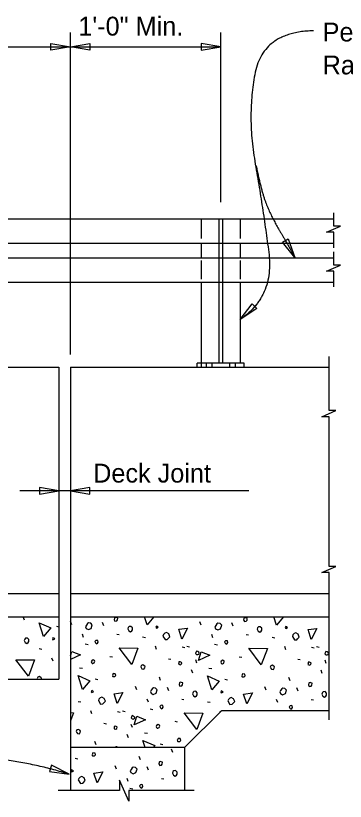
# Model space of a CAD drawing. Extents: x 120680.2 to 120752.3, y 120667.6 to 120707.3.
# Drawn here: x 120701.61 to 120705.13, y 120695.16 to 120703.55 of the extents above; entities that cross this region are included whole.
import ezdxf

# ---------------------------------------------------------------- set-up
doc = ezdxf.new("R2010")
doc.units = 0
for name, color, linetype in [('Dimension', 7, 'Continuous'), ('ParapetConc', 7, 'Continuous'), ('PedRail', 7, 'Continuous'), ('TextStructures', 7, 'Continuous')]:
    doc.layers.add(name, color=color, linetype=linetype)

msp = doc.modelspace()

# ---------------------------------------------------------------- linework, layer by layer
at = {"layer": 'Dimension'}
for p, q in [((120702.1898, 120699.9295), (120702.1898, 120703.3696)), ((120703.7953, 120701.556), (120703.7953, 120703.3696)), ((120698.746, 120703.2151), (120702.1898, 120703.2151)), ((120704.094, 120698.4727), (120701.6496, 120698.4727))]:
    msp.add_line(p, q, dxfattribs=at)
for points in [[(120701.9815, 120703.2503), (120702.1898, 120703.2151), (120701.9815, 120703.1798)], [(120702.398, 120703.1798), (120702.1898, 120703.2151), (120702.398, 120703.2503)], [(120703.7953, 120703.2151), (120703.587, 120703.2503), (120703.587, 120703.1798)], [(120704.5166, 120701.1656), (120704.5874, 120700.9666), (120704.455, 120701.1312)], [(120704.1797, 120700.4209), (120704.0036, 120700.3043), (120704.1314, 120700.4724)], [(120702.0673, 120698.4727), (120701.859, 120698.5079), (120701.859, 120698.4374)], [(120702.1898, 120698.4727), (120702.398, 120698.4374), (120702.398, 120698.5079)], [(120702.1768, 120695.4468), (120701.9878, 120695.5411), (120701.9673, 120695.4736)]]:
    msp.add_lwpolyline(points, close=True, dxfattribs=at)
for points in [[(120702.1898, 120703.2151), (120703.7953, 120703.2151)], [(120705.0043, 120701.069), (120705.0043, 120701.2356), (120704.9268, 120701.2356), (120705.0768, 120701.3018), (120705.0043, 120701.3018), (120705.0043, 120701.4427)], [(120705.0043, 120700.7007), (120705.0043, 120700.8189), (120704.9268, 120700.8189), (120705.0768, 120700.8852), (120705.0043, 120700.8852), (120705.0043, 120701.026)], [(120705.0043, 120700.6523), (120705.0043, 120700.7007)], [(120704.9532, 120698.3779), (120704.9532, 120699.2651), (120704.8757, 120699.2651), (120705.0257, 120699.3314), (120704.9532, 120699.3314), (120704.9532, 120699.907)], [(120704.9532, 120696.0279), (120704.9532, 120697.6005), (120704.8757, 120697.6005), (120705.0257, 120697.6668), (120704.9532, 120697.6668), (120704.9532, 120698.3779)], [(120703.5106, 120695.2732), (120702.8136, 120695.2732), (120702.8136, 120695.157), (120702.7142, 120695.382), (120702.7142, 120695.2732), (120702.059, 120695.2732)]]:
    msp.add_lwpolyline(points, dxfattribs=at)
for points in [[(120704.7863, 120703.3873), (120704.2451, 120703.3779), (120704.0759, 120702.477), (120704.2447, 120701.5052), (120704.371, 120700.5545), (120704.0036, 120700.3043)], [(120704.1744, 120701.9453), (120704.2306, 120701.6629), (120704.3399, 120701.3964), (120704.4841, 120701.1516), (120704.5874, 120700.9666)], [(120702.1768, 120695.4468), (120701.526, 120695.6444), (120700.8623, 120695.6444)]]:
    msp.add_open_spline(points, degree=2, dxfattribs=at)
at = {"layer": 'ParapetConc'}
for p, q in [((120695.9996, 120699.7946), (120702.0673, 120699.7946)), ((120702.0673, 120699.7946), (120702.0673, 120696.4613)), ((120702.1898, 120699.7946), (120702.1898, 120695.2732)), ((120702.1898, 120699.7946), (120704.9532, 120699.7946)), ((120695.9996, 120697.3779), (120702.0673, 120697.3779)), ((120702.1898, 120697.3779), (120704.9532, 120697.3779)), ((120695.9996, 120697.1279), (120702.0673, 120697.1279)), ((120702.1898, 120697.1279), (120704.9532, 120697.1279)), ((120695.9996, 120696.4612), (120702.0673, 120696.4612)), ((120703.4098, 120695.7305), (120703.8071, 120696.1279)), ((120703.8071, 120696.1279), (120704.9532, 120696.1279)), ((120703.4098, 120695.7305), (120702.1898, 120695.7305)), ((120703.4098, 120695.7305), (120703.4098, 120695.2732))]:
    msp.add_line(p, q, dxfattribs=at)
at = {"layer": 'PedRail'}
for p, q in [((120700.4577, 120701.3779), (120705.0043, 120701.3779)), ((120703.5869, 120701.3779), (120703.5869, 120701.1671)), ((120703.7744, 120701.3779), (120703.7744, 120700.7007)), ((120703.8161, 120701.3779), (120703.8161, 120700.7007)), ((120704.0036, 120701.3779), (120704.0036, 120701.1671)), ((120700.4577, 120701.1174), (120705.0043, 120701.1174)), ((120703.5869, 120701.1084), (120703.5869, 120700.9613)), ((120704.0036, 120701.1084), (120704.0036, 120700.9613)), ((120700.4577, 120700.9613), (120703.5869, 120700.9613)), ((120702.1735, 120700.9613), (120705.0043, 120700.9613)), ((120703.5869, 120700.9345), (120703.5869, 120700.7342)), ((120704.0036, 120700.9345), (120704.0036, 120700.7342)), ((120700.4577, 120700.7007), (120703.5869, 120700.7007)), ((120702.1735, 120700.7007), (120705.0043, 120700.7007)), ((120703.5869, 120700.7007), (120703.5869, 120699.7946)), ((120703.7744, 120700.7007), (120703.7744, 120699.8363)), ((120703.8161, 120700.7007), (120703.8161, 120699.8363)), ((120704.0036, 120700.7007), (120704.0036, 120699.8363)), ((120704.0453, 120699.8363), (120703.5453, 120699.8363)), ((120703.5453, 120699.7946), (120703.5453, 120699.8363)), ((120703.639, 120699.8363), (120703.639, 120699.7946)), ((120703.7015, 120699.8363), (120703.7015, 120699.7946)), ((120703.889, 120699.8363), (120703.889, 120699.7946)), ((120703.9515, 120699.8363), (120703.9515, 120699.7946)), ((120704.0453, 120699.7946), (120704.0453, 120699.8363)), ((120701.6998, 120697.0923), (120701.6856, 120697.1277)), ((120702.2045, 120697.0405), (120702.1904, 120697.0759)), ((120702.5475, 120697.0299), (120702.5333, 120697.0653)), ((120703.5869, 120697.037), (120703.5728, 120697.0723)), ((120703.9298, 120697.0264), (120703.9157, 120697.0618)), ((120702.0392, 120697.0287), (120702.0673, 120697.0217)), ((120702.33, 120696.908), (120702.3176, 120696.9416)), ((120702.6854, 120696.9416), (120702.7101, 120696.938)), ((120702.9611, 120696.9133), (120702.9912, 120696.908)), ((120703.7124, 120696.9044), (120703.7, 120696.938)), ((120704.0678, 120696.938), (120704.0925, 120696.9345)), ((120704.3435, 120696.9097), (120704.3736, 120696.9044)), ((120701.8554, 120696.7883), (120701.8854, 120696.783)), ((120702.3477, 120696.8372), (120702.3778, 120696.8319)), ((120703.1096, 120696.7789), (120703.0972, 120696.8125)), ((120703.3836, 120696.8054), (120703.4119, 120696.7983)), ((120703.4349, 120696.8143), (120703.4632, 120696.8072)), ((120703.7301, 120696.8337), (120703.7601, 120696.8284)), ((120704.492, 120696.7754), (120704.4796, 120696.809)), ((120704.766, 120696.8019), (120704.7943, 120696.7948)), ((120704.8173, 120696.8107), (120704.8456, 120696.8036)), ((120702.6111, 120696.7047), (120702.6376, 120696.6994)), ((120703.9935, 120696.7011), (120704.02, 120696.6958)), ((120702.0038, 120696.6539), (120701.9914, 120696.6875)), ((120703.2369, 120696.6799), (120703.2634, 120696.6746)), ((120703.5409, 120696.634), (120703.5286, 120696.6676)), ((120704.6193, 120696.6764), (120704.6458, 120696.6711)), ((120704.9233, 120696.6304), (120704.911, 120696.664)), ((120702.2876, 120696.5827), (120702.3194, 120696.5792)), ((120703.4985, 120696.5244), (120703.4844, 120696.5597)), ((120703.67, 120696.5792), (120703.7018, 120696.5756)), ((120704.8809, 120696.5208), (120704.8668, 120696.5562)), ((120702.4556, 120696.4643), (120702.4838, 120696.4572)), ((120703.1538, 120696.4483), (120703.1397, 120696.4837)), ((120703.838, 120696.4607), (120703.8662, 120696.4536)), ((120704.5362, 120696.4448), (120704.5221, 120696.4802)), ((120702.8975, 120696.3476), (120702.8833, 120696.3829)), ((120703.2404, 120696.337), (120703.2263, 120696.3723)), ((120704.2799, 120696.3441), (120704.2657, 120696.3794)), ((120704.6228, 120696.3334), (120704.6087, 120696.3688)), ((120702.2717, 120696.2239), (120702.3018, 120696.2185)), ((120703.023, 120696.215), (120703.0106, 120696.2486)), ((120703.3783, 120696.2486), (120703.4031, 120696.2451)), ((120703.6541, 120696.2203), (120703.6842, 120696.215)), ((120704.4054, 120696.2115), (120704.393, 120696.2451)), ((120704.7607, 120696.2451), (120704.7855, 120696.2415)), ((120702.4202, 120696.0895), (120702.4078, 120696.1231)), ((120702.6942, 120696.116), (120702.7225, 120696.1089)), ((120702.7455, 120696.1248), (120702.7737, 120696.1178)), ((120703.0407, 120696.1443), (120703.0707, 120696.139)), ((120703.7925, 120696.1133), (120703.7902, 120696.1195)), ((120702.5475, 120695.9905), (120702.574, 120695.9852)), ((120702.8515, 120695.9445), (120702.8392, 120695.9781)), ((120703.3041, 120696.0117), (120703.3306, 120696.0064)), ((120702.8091, 120695.8349), (120702.7949, 120695.8703)), ((120702.9806, 120695.8897), (120703.0124, 120695.8862)), ((120702.4644, 120695.7589), (120702.4503, 120695.7943)), ((120703.1485, 120695.7713), (120703.1768, 120695.7642)), ((120703.2828, 120695.677), (120703.2686, 120695.7123)), ((120702.2398, 120695.6169), (120702.2681, 120695.6098)), ((120702.9381, 120695.601), (120702.9239, 120695.6364)), ((120702.6818, 120695.5002), (120702.6676, 120695.5356)), ((120703.0247, 120695.4896), (120703.0106, 120695.525)), ((120702.8073, 120695.3677), (120702.7949, 120695.4013)), ((120703.1626, 120695.4013), (120703.1873, 120695.3977)), ((120702.8249, 120695.2969), (120702.855, 120695.2916))]:
    msp.add_line(p, q, dxfattribs=at)
for points in [[(120702.6571, 120697.0971), (120702.6659, 120697.0812), (120702.6854, 120697.083), (120702.6942, 120697.0954), (120702.696, 120697.1148), (120702.6836, 120697.1201), (120702.6747, 120697.1219), (120702.6642, 120697.1183), (120702.6606, 120697.1148), (120702.6571, 120697.0971)], [(120703.0088, 120697.0423), (120702.981, 120697.1279)], [(120703.0813, 120697.1279), (120703.0088, 120697.0423)], [(120704.3912, 120697.0388), (120704.3623, 120697.1279)], [(120704.4667, 120697.1279), (120704.3912, 120697.0388)], [(120701.9031, 120696.9173), (120701.8554, 120697.0641), (120701.9809, 120697.0092), (120701.9031, 120696.9173)], [(120702.3583, 120697.0034), (120702.3813, 120696.991), (120702.4113, 120697.0034), (120702.4237, 120697.0405), (120702.406, 120697.0582), (120702.3831, 120697.0635), (120702.3724, 120697.0565), (120702.3601, 120697.037), (120702.3512, 120697.0211), (120702.3583, 120697.0034)], [(120703.7407, 120696.9999), (120703.7637, 120696.9875), (120703.7937, 120696.9999), (120703.8061, 120697.037), (120703.7884, 120697.0547), (120703.7655, 120697.06), (120703.7548, 120697.0529), (120703.7425, 120697.0335), (120703.7336, 120697.0176), (120703.7407, 120696.9999)], [(120704.0395, 120697.0936), (120704.0483, 120697.0777), (120704.0678, 120697.0794), (120704.0766, 120697.0918), (120704.0784, 120697.1113), (120704.066, 120697.1166), (120704.0571, 120697.1183), (120704.0466, 120697.1148), (120704.043, 120697.1113), (120704.0395, 120697.0936)], [(120702.802, 120696.9981), (120702.8126, 120696.9769), (120702.8303, 120696.9663), (120702.8445, 120696.9769), (120702.8515, 120696.9875), (120702.8515, 120697.0087), (120702.8356, 120697.0246), (120702.8162, 120697.0229), (120702.8073, 120697.014), (120702.802, 120696.9981)], [(120703.1079, 120697.007), (120703.1273, 120697.0158), (120703.1202, 120697.0229), (120703.1079, 120697.0282), (120703.1025, 120697.0158), (120703.1079, 120697.007)], [(120703.1786, 120696.9221), (120703.2016, 120696.885), (120703.2245, 120696.8868), (120703.2334, 120696.8956), (120703.2528, 120696.9151), (120703.2404, 120696.9451), (120703.2157, 120696.9592), (120703.198, 120696.9521), (120703.1838, 120696.938), (120703.1786, 120696.9221)], [(120703.3801, 120696.8903), (120703.3465, 120696.9946), (120703.4402, 120697.007), (120703.3801, 120696.8903)], [(120704.1844, 120696.9946), (120704.195, 120696.9734), (120704.2127, 120696.9628), (120704.2269, 120696.9734), (120704.2339, 120696.984), (120704.2339, 120697.0052), (120704.218, 120697.0211), (120704.1986, 120697.0193), (120704.1897, 120697.0105), (120704.1844, 120696.9946)], [(120704.4903, 120697.0034), (120704.5097, 120697.0122), (120704.5026, 120697.0193), (120704.4903, 120697.0246), (120704.4849, 120697.0122), (120704.4903, 120697.0034)], [(120704.5609, 120696.9185), (120704.5839, 120696.8815), (120704.6069, 120696.8832), (120704.6158, 120696.892), (120704.6352, 120696.9115), (120704.6228, 120696.9416), (120704.5981, 120696.9557), (120704.5804, 120696.9486), (120704.5662, 120696.9345), (120704.5609, 120696.9185)], [(120704.7625, 120696.8868), (120704.7289, 120696.991), (120704.8226, 120697.0034), (120704.7625, 120696.8868)], [(120701.6962, 120696.8731), (120701.7069, 120696.8519), (120701.7245, 120696.8413), (120701.7387, 120696.8519), (120701.7457, 120696.8625), (120701.7457, 120696.8838), (120701.7298, 120696.8996), (120701.7104, 120696.8979), (120701.7016, 120696.8891), (120701.6962, 120696.8731)], [(120702.0021, 120696.882), (120702.0215, 120696.8908), (120702.0144, 120696.8979), (120702.0021, 120696.9032), (120701.9968, 120696.8908), (120702.0021, 120696.882)], [(120702.4591, 120696.8496), (120702.4697, 120696.839), (120702.4803, 120696.8461), (120702.4874, 120696.8567), (120702.4838, 120696.8744), (120702.475, 120696.8761), (120702.4626, 120696.8744), (120702.452, 120696.8638), (120702.4591, 120696.8496)], [(120703.8414, 120696.8461), (120703.8521, 120696.8355), (120703.8627, 120696.8426), (120703.8698, 120696.8532), (120703.8662, 120696.8708), (120703.8574, 120696.8726), (120703.845, 120696.8708), (120703.8344, 120696.8602), (120703.8414, 120696.8461)], [(120702.8462, 120696.618), (120702.7119, 120696.7948), (120702.9116, 120696.7931), (120702.8462, 120696.618)], [(120704.2286, 120696.6145), (120704.0943, 120696.7913), (120704.294, 120696.7895), (120704.2286, 120696.6145)], [(120702.1898, 120696.7098), (120702.2045, 120696.7577), (120702.2982, 120696.7206), (120702.1898, 120696.6719)], [(120703.5374, 120696.7259), (120703.5498, 120696.7241), (120703.5622, 120696.7294), (120703.5657, 120696.74), (120703.5604, 120696.7489), (120703.5498, 120696.7559), (120703.5374, 120696.7613), (120703.5304, 120696.7471), (120703.5268, 120696.7365), (120703.5374, 120696.7259)], [(120703.5586, 120696.6622), (120703.5869, 120696.7542), (120703.6806, 120696.717), (120703.5586, 120696.6622)], [(120704.9198, 120696.7223), (120704.9322, 120696.7206), (120704.9446, 120696.7259), (120704.9481, 120696.7365), (120704.9428, 120696.7453), (120704.9322, 120696.7524), (120704.9198, 120696.7577), (120704.9128, 120696.7435), (120704.9092, 120696.733), (120704.9198, 120696.7223)], [(120701.7405, 120696.4931), (120701.6061, 120696.6698), (120701.8058, 120696.6681), (120701.7405, 120696.4931)], [(120702.4237, 120696.6304), (120702.4308, 120696.6304), (120702.4449, 120696.6375), (120702.4503, 120696.6534), (120702.4485, 120696.6622), (120702.4343, 120696.6693), (120702.4167, 120696.6587), (120702.4131, 120696.6481), (120702.4167, 120696.6375), (120702.4237, 120696.6304)], [(120703.3447, 120696.6216), (120703.3642, 120696.6163), (120703.3766, 120696.6251), (120703.3783, 120696.6375), (120703.3748, 120696.641), (120703.3606, 120696.6481), (120703.3483, 120696.6464), (120703.3465, 120696.634), (120703.3447, 120696.6216)], [(120703.8061, 120696.6269), (120703.8132, 120696.6269), (120703.8273, 120696.634), (120703.8326, 120696.6498), (120703.8309, 120696.6587), (120703.8167, 120696.6658), (120703.7991, 120696.6552), (120703.7955, 120696.6446), (120703.7991, 120696.634), (120703.8061, 120696.6269)], [(120704.7271, 120696.618), (120704.7466, 120696.6128), (120704.7589, 120696.6216), (120704.7607, 120696.634), (120704.7572, 120696.6375), (120704.743, 120696.6446), (120704.7307, 120696.6428), (120704.7289, 120696.6304), (120704.7271, 120696.618)], [(120702.9452, 120696.5863), (120702.9541, 120696.5703), (120702.9753, 120696.5668), (120702.9841, 120696.5827), (120702.9876, 120696.5968), (120702.9788, 120696.6057), (120702.9629, 120696.6145), (120702.947, 120696.6092), (120702.9417, 120696.5933), (120702.9452, 120696.5863)], [(120704.3276, 120696.5827), (120704.3364, 120696.5668), (120704.3576, 120696.5632), (120704.3665, 120696.5792), (120704.37, 120696.5933), (120704.3612, 120696.6021), (120704.3453, 120696.611), (120704.3294, 120696.6057), (120704.3241, 120696.5897), (120704.3276, 120696.5827)], [(120701.8792, 120696.4613), (120701.8819, 120696.4718), (120701.873, 120696.4807), (120701.8571, 120696.4895), (120701.8412, 120696.4842), (120701.8359, 120696.4683), (120701.8394, 120696.4613)], [(120702.3194, 120696.3529), (120702.2717, 120696.4996), (120702.3972, 120696.4448), (120702.3194, 120696.3529)], [(120702.6429, 120696.489), (120702.6642, 120696.489), (120702.6747, 120696.4996), (120702.6694, 120696.5191), (120702.6464, 120696.5208), (120702.6429, 120696.5102), (120702.6376, 120696.5014), (120702.6429, 120696.489), (120702.6394, 120696.4926)], [(120703.7018, 120696.3493), (120703.6541, 120696.4961), (120703.7796, 120696.4413), (120703.7018, 120696.3493)], [(120704.0253, 120696.4855), (120704.0466, 120696.4855), (120704.0571, 120696.4961), (120704.0518, 120696.5155), (120704.0288, 120696.5173), (120704.0253, 120696.5067), (120704.02, 120696.4978), (120704.0253, 120696.4855), (120704.0218, 120696.489)], [(120703.0513, 120696.3105), (120703.0743, 120696.2981), (120703.1043, 120696.3105), (120703.1167, 120696.3476), (120703.099, 120696.3653), (120703.076, 120696.3706), (120703.0654, 120696.3635), (120703.0531, 120696.3441), (120703.0442, 120696.3281), (120703.0513, 120696.3105)], [(120703.35, 120696.4042), (120703.3589, 120696.3882), (120703.3783, 120696.39), (120703.3872, 120696.4024), (120703.3889, 120696.4218), (120703.3766, 120696.4271), (120703.3677, 120696.4289), (120703.3571, 120696.4254), (120703.3536, 120696.4218), (120703.35, 120696.4042)], [(120704.4337, 120696.3069), (120704.4567, 120696.2945), (120704.4867, 120696.3069), (120704.4991, 120696.3441), (120704.4814, 120696.3617), (120704.4584, 120696.367), (120704.4478, 120696.3599), (120704.4355, 120696.3405), (120704.4266, 120696.3246), (120704.4337, 120696.3069)], [(120704.7324, 120696.4006), (120704.7412, 120696.3847), (120704.7607, 120696.3865), (120704.7696, 120696.3989), (120704.7713, 120696.4183), (120704.7589, 120696.4236), (120704.7501, 120696.4254), (120704.7395, 120696.4218), (120704.736, 120696.4183), (120704.7324, 120696.4006)], [(120702.4184, 120696.3175), (120702.4379, 120696.3264), (120702.4308, 120696.3334), (120702.4184, 120696.3388), (120702.4131, 120696.3264), (120702.4184, 120696.3175)], [(120702.6907, 120696.2008), (120702.6571, 120696.3052), (120702.7508, 120696.3175), (120702.6907, 120696.2008)], [(120703.495, 120696.3052), (120703.5056, 120696.284), (120703.5233, 120696.2733), (120703.5374, 120696.284), (120703.5445, 120696.2945), (120703.5445, 120696.3158), (120703.5286, 120696.3317), (120703.5092, 120696.3299), (120703.5003, 120696.321), (120703.495, 120696.3052)], [(120703.8008, 120696.314), (120703.8203, 120696.3228), (120703.8132, 120696.3299), (120703.8008, 120696.3352), (120703.7955, 120696.3228), (120703.8008, 120696.314)], [(120704.0731, 120696.1973), (120704.0395, 120696.3016), (120704.1332, 120696.314), (120704.0731, 120696.1973)], [(120704.8774, 120696.3016), (120704.888, 120696.2804), (120704.9057, 120696.2698), (120704.9198, 120696.2804), (120704.9269, 120696.291), (120704.9269, 120696.3122), (120704.911, 120696.3281), (120704.8915, 120696.3264), (120704.8827, 120696.3175), (120704.8774, 120696.3016)], [(120702.4891, 120696.2327), (120702.5121, 120696.1956), (120702.5351, 120696.1973), (120702.5439, 120696.2061), (120702.5634, 120696.2256), (120702.551, 120696.2557), (120702.5262, 120696.2698), (120702.5086, 120696.2627), (120702.4944, 120696.2486), (120702.4891, 120696.2327)], [(120703.8715, 120696.2291), (120703.8945, 120696.192), (120703.9175, 120696.1938), (120703.9263, 120696.2026), (120703.9458, 120696.2221), (120703.9334, 120696.2521), (120703.9086, 120696.2663), (120703.891, 120696.2592), (120703.8768, 120696.2451), (120703.8715, 120696.2291)], [(120703.152, 120696.1567), (120703.1626, 120696.146), (120703.1733, 120696.1531), (120703.1803, 120696.1638), (120703.1768, 120696.1814), (120703.168, 120696.1832), (120703.1556, 120696.1814), (120703.145, 120696.1708), (120703.152, 120696.1567)], [(120704.5344, 120696.1531), (120704.545, 120696.1425), (120704.5557, 120696.1496), (120704.5627, 120696.1602), (120704.5592, 120696.1779), (120704.5504, 120696.1796), (120704.538, 120696.1779), (120704.5274, 120696.1672), (120704.5344, 120696.1531)], [(120702.1898, 120696.104), (120702.2222, 120696.1036), (120702.1898, 120696.0169)], [(120702.848, 120696.0365), (120702.8604, 120696.0347), (120702.8728, 120696.04), (120702.8763, 120696.0506), (120702.871, 120696.0594), (120702.8604, 120696.0665), (120702.848, 120696.0718), (120702.8409, 120696.0577), (120702.8374, 120696.047), (120702.848, 120696.0365)], [(120702.8692, 120695.9728), (120702.8975, 120696.0647), (120702.9912, 120696.0276), (120702.8692, 120695.9728)], [(120703.5392, 120695.9251), (120703.4048, 120696.1019), (120703.6046, 120696.1001), (120703.5392, 120695.9251)], [(120702.6553, 120695.9321), (120702.6747, 120695.9268), (120702.6871, 120695.9357), (120702.6889, 120695.9481), (120702.6854, 120695.9516), (120702.6712, 120695.9586), (120702.6588, 120695.9569), (120702.6571, 120695.9445), (120702.6553, 120695.9321)], [(120703.1167, 120695.9374), (120703.1237, 120695.9374), (120703.1379, 120695.9445), (120703.1432, 120695.9604), (120703.1414, 120695.9693), (120703.1273, 120695.9764), (120703.1096, 120695.9657), (120703.1061, 120695.9552), (120703.1096, 120695.9445), (120703.1167, 120695.9374)], [(120702.2558, 120695.8968), (120702.2646, 120695.8809), (120702.2858, 120695.8773), (120702.2947, 120695.8933), (120702.2982, 120695.9074), (120702.2894, 120695.9163), (120702.2735, 120695.9251), (120702.2575, 120695.9198), (120702.2522, 120695.9039), (120702.2558, 120695.8968)], [(120702.9894, 120695.7305), (120702.9647, 120695.8066), (120703.0901, 120695.7518), (120703.0721, 120695.7305)], [(120703.3359, 120695.796), (120703.3571, 120695.796), (120703.3677, 120695.8066), (120703.3624, 120695.8261), (120703.3394, 120695.8279), (120703.3359, 120695.8172), (120703.3306, 120695.8084), (120703.3359, 120695.796), (120703.3323, 120695.7996)], [(120702.6993, 120695.7305), (120702.6995, 120695.7324), (120702.6871, 120695.7377), (120702.6783, 120695.7395), (120702.6677, 120695.7359), (120702.6642, 120695.7324), (120702.6638, 120695.7305)], [(120702.4272, 120695.6417), (120702.4484, 120695.6417), (120702.459, 120695.6522), (120702.4537, 120695.6717), (120702.4307, 120695.6735), (120702.4272, 120695.6629), (120702.4219, 120695.654), (120702.4272, 120695.6417), (120702.4236, 120695.6452)], [(120703.1343, 120695.5568), (120703.1432, 120695.5409), (120703.1626, 120695.5427), (120703.1714, 120695.5551), (120703.1732, 120695.5745), (120703.1608, 120695.5798), (120703.152, 120695.5816), (120703.1414, 120695.578), (120703.1379, 120695.5745), (120703.1343, 120695.5568)], [(120702.2027, 120695.4702), (120702.2221, 120695.479), (120702.215, 120695.4861), (120702.2027, 120695.4914), (120702.1974, 120695.479), (120702.2027, 120695.4702)], [(120702.4749, 120695.3535), (120702.4413, 120695.4578), (120702.535, 120695.4702), (120702.4749, 120695.3535)], [(120702.8356, 120695.4631), (120702.8585, 120695.4507), (120702.8886, 120695.4631), (120702.901, 120695.5002), (120702.8833, 120695.5179), (120702.8603, 120695.5232), (120702.8497, 120695.5161), (120702.8373, 120695.4967), (120702.8285, 120695.4808), (120702.8356, 120695.4631)], [(120703.2793, 120695.4578), (120703.2899, 120695.4366), (120703.3075, 120695.426), (120703.3217, 120695.4366), (120703.3287, 120695.4472), (120703.3287, 120695.4684), (120703.3129, 120695.4843), (120703.2934, 120695.4826), (120703.2846, 120695.4737), (120703.2793, 120695.4578)], [(120702.2734, 120695.3853), (120702.2964, 120695.3482), (120702.3194, 120695.3499), (120702.3282, 120695.3588), (120702.3476, 120695.3783), (120702.3353, 120695.4083), (120702.3105, 120695.4224), (120702.2929, 120695.4154), (120702.2787, 120695.4013), (120702.2734, 120695.3853)], [(120702.9363, 120695.3093), (120702.9469, 120695.2987), (120702.9575, 120695.3058), (120702.9646, 120695.3164), (120702.9611, 120695.3341), (120702.9522, 120695.3358), (120702.9398, 120695.3341), (120702.9293, 120695.3234), (120702.9363, 120695.3093)]]:
    msp.add_lwpolyline(points, dxfattribs=at)

# ---------------------------------------------------------------- texts
at = {"layer": 'TextStructures'}
for s, p in [('1\'-0" Min.', (120702.2743, 120703.3364)), ('Pedestrian/Bicycle', (120704.8842, 120703.2738)), ('Railing ', (120704.8842, 120702.9218)), ('Deck Joint', (120702.4325, 120698.5616))]:
    msp.add_text(s, height=0.2016, dxfattribs=at).set_placement(p)

doc.saveas('drawing.dxf')
